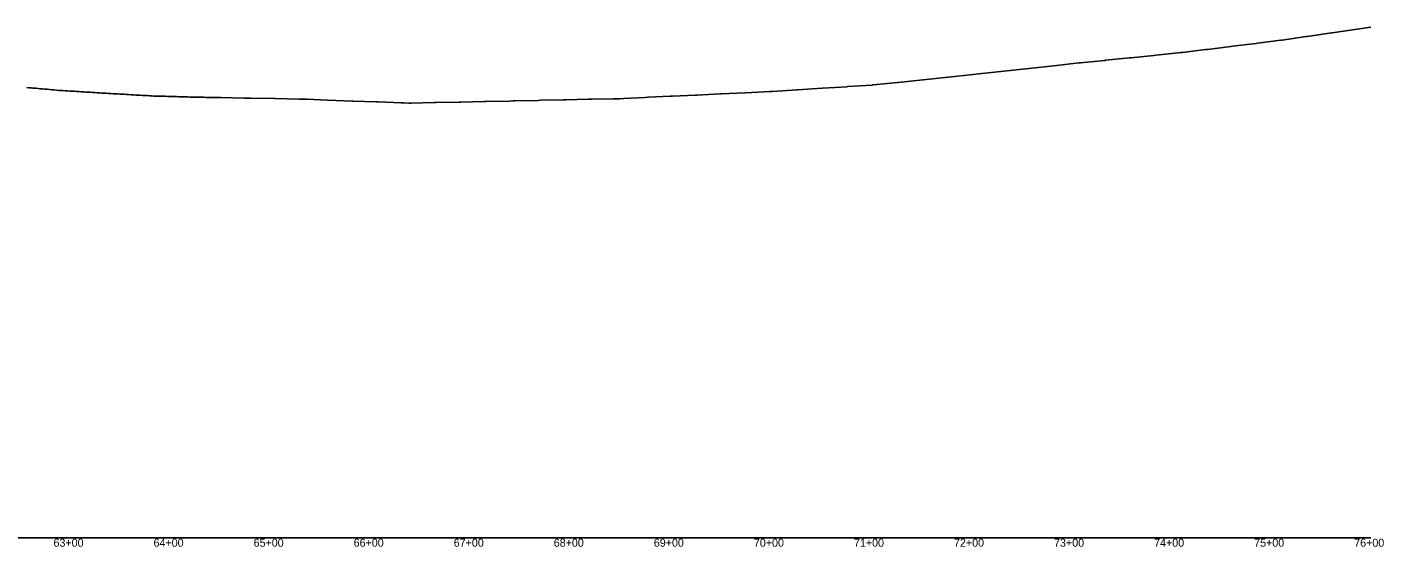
# Model space of a CAD drawing. Extents: x 49922 to 52614, y 49991 to 60509.
# Drawn here: x 51257 to 52613, y 49991 to 50510 of the extents above; entities that cross this region are included whole.
import ezdxf

# ---------------------------------------------------------------- set-up
doc = ezdxf.new("R2010")
doc.units = 0
for name, color, linetype in [('RD_DDB_Profile_EX', 7, 'Continuous'), ('RD_DDB_StaTX', 7, 'Continuous'), ('RD_GPK_Profile_Cell', 7, 'Continuous')]:
    doc.layers.add(name, color=color, linetype=linetype)

msp = doc.modelspace()

# ---------------------------------------------------------------- linework, layer by layer
at = {"layer": 'RD_DDB_Profile_EX'}
for points in [[(51853.4, 50438.6), (51874.5, 50439.6), (51877.8, 50439.8), (51899.6, 50440.8), (51902.1, 50440.9), (51924.6, 50442), (51926.4, 50442.1), (51949.6, 50443.2), (51950.7, 50443.2), (51974.7, 50444.4), (51975, 50444.4), (51987.6, 50445), (51999.4, 50445.5), (51999.7, 50445.5), (52002, 50445.6), (52026.6, 50447.2), (52027, 50447.2), (52051.6, 50448.8), (52052, 50448.8), (52076.6, 50450.4), (52077, 50450.5), (52101.6, 50452), (52102, 50452.1), (52102.5, 50452.1), (52127.1, 50454.7), (52127.5, 50454.7), (52152.2, 50457.3), (52152.5, 50457.3), (52177.5, 50459.9), (52202.5, 50462.5), (52208.2, 50463.1), (52233.2, 50465.9), (52258.2, 50468.6), (52283.2, 50471.4), (52308.1, 50474.1), (52309.8, 50474.3), (52334.1, 50476.7), (52334.9, 50476.8), (52358.6, 50479.2), (52359.9, 50479.3), (52383, 50481.7), (52384.9, 50481.9), (52407.5, 50484.1), (52410, 50484.4), (52411.8, 50484.6), (52434.6, 50487.4), (52436.8, 50487.7), (52459.9, 50490.5), (52461.8, 50490.8), (52485.2, 50493.7), (52486.8, 50493.9), (52510, 50496.7), (52511.2, 50496.9), (52535.3, 50500.4), (52536.2, 50500.5), (52560.6, 50504.1), (52561.2, 50504.2), (52586.3, 50507.8), (52600, 50509.9)], [(51256.5, 50449.5), (51258.8, 50449.4), (51261, 50449.2), (51262.8, 50449), (51263.3, 50449), (51265.6, 50448.8), (51267.9, 50448.5), (51270.1, 50448.4), (51272.4, 50448.2), (51274.7, 50448), (51276.9, 50447.8), (51279.2, 50447.6), (51281.5, 50447.4), (51283.7, 50447.2), (51286, 50447), (51288.5, 50446.7), (51290.6, 50446.6), (51292.8, 50446.5), (51295.1, 50446.4), (51297.4, 50446.3), (51299.6, 50446.1), (51301.9, 50446), (51304.2, 50445.8), (51306.4, 50445.7), (51308.7, 50445.6), (51311, 50445.4), (51312.1, 50445.4), (51313.5, 50445.3), (51315.5, 50445.1)], [(51315.5, 50445.1), (51317.8, 50445), (51320.1, 50444.8), (51322.3, 50444.7), (51324.6, 50444.5), (51326.9, 50444.4), (51329.2, 50444.2), (51331.4, 50444.1), (51333.4, 50443.9), (51333.7, 50443.9), (51336, 50443.8), (51338.2, 50443.7), (51340.5, 50443.6), (51342.8, 50443.4), (51345, 50443.3), (51347.3, 50443.2), (51349.6, 50443.1), (51351.9, 50442.9), (51354.1, 50442.8), (51356.4, 50442.7), (51358.3, 50442.6), (51358.7, 50442.5), (51360.9, 50442.4), (51361.3, 50442.3), (51363.2, 50442.2), (51365.5, 50442.1), (51367.7, 50442), (51370, 50441.8), (51372.3, 50441.7), (51374.6, 50441.6), (51376.8, 50441.5), (51379.3, 50441.3), (51381.4, 50441.2), (51383.6, 50441.1), (51385.9, 50441), (51388.2, 50441), (51390.5, 50440.9), (51392.7, 50440.8), (51395, 50440.8), (51397.3, 50440.7), (51399.5, 50440.6), (51401.8, 50440.6), (51404.3, 50440.5), (51406.3, 50440.5), (51408.6, 50440.4), (51410.9, 50440.3), (51413.2, 50440.3), (51415.4, 50440.2), (51417.7, 50440.2), (51420, 50440.1), (51422.2, 50440.1), (51424.5, 50440), (51425.8, 50439.9), (51426.8, 50439.9), (51429.1, 50439.8), (51431.3, 50439.8), (51433.6, 50439.8), (51435.9, 50439.7), (51438.1, 50439.7), (51440.4, 50439.7), (51447.7, 50439.5), (51450.7, 50439.5), (51474.3, 50439.1), (51475.9, 50439.1), (51479.2, 50439), (51480.3, 50439), (51504.2, 50438.5), (51504.8, 50438.5), (51529.3, 50438.1), (51532.9, 50438), (51536.7, 50437.9), (51557.3, 50437.1), (51557.8, 50437.1), (51581.8, 50436.1), (51582.8, 50436.1), (51606.2, 50435.2), (51607.8, 50435.2), (51630.7, 50434.3), (51632.8, 50434.2), (51633.2, 50434.2), (51638.6, 50434), (51640.9, 50434.1), (51663.7, 50434.5), (51665.7, 50434.6), (51688.7, 50435.1), (51690.5, 50435.1), (51713.7, 50435.6), (51715.3, 50435.6), (51738.9, 50436.1), (51742.7, 50436.2), (51744, 50436.2), (51767.7, 50436.7), (51769.6, 50436.8), (51792.7, 50437.2), (51795.3, 50437.3), (51817.6, 50437.8), (51820.9, 50437.8), (51842.6, 50438.3), (51843.6, 50438.3), (51849.5, 50438.4), (51853.4, 50438.6)]]:
    msp.add_lwpolyline(points, dxfattribs=at)
at = {"layer": 'RD_GPK_Profile_Cell'}
msp.add_line((50000, 50000), (52600, 50000), dxfattribs=at)

# ---------------------------------------------------------------- texts
at = {"layer": 'RD_DDB_StaTX'}
for s, p in [('63+00', (51283.3, 49991)), ('64+00', (51383.3, 49991)), ('65+00', (51483.3, 49991)), ('66+00', (51583.3, 49991)), ('67+00', (51683.3, 49991)), ('68+00', (51783.3, 49991)), ('69+00', (51883.3, 49991)), ('70+00', (51983.3, 49991)), ('71+00', (52083.3, 49991)), ('72+00', (52183.3, 49991)), ('73+00', (52283.3, 49991)), ('74+00', (52383.3, 49991)), ('75+00', (52483.3, 49991)), ('76+00', (52583.3, 49991))]:
    msp.add_text(s, height=8, dxfattribs=at).set_placement(p)

doc.saveas('drawing.dxf')
